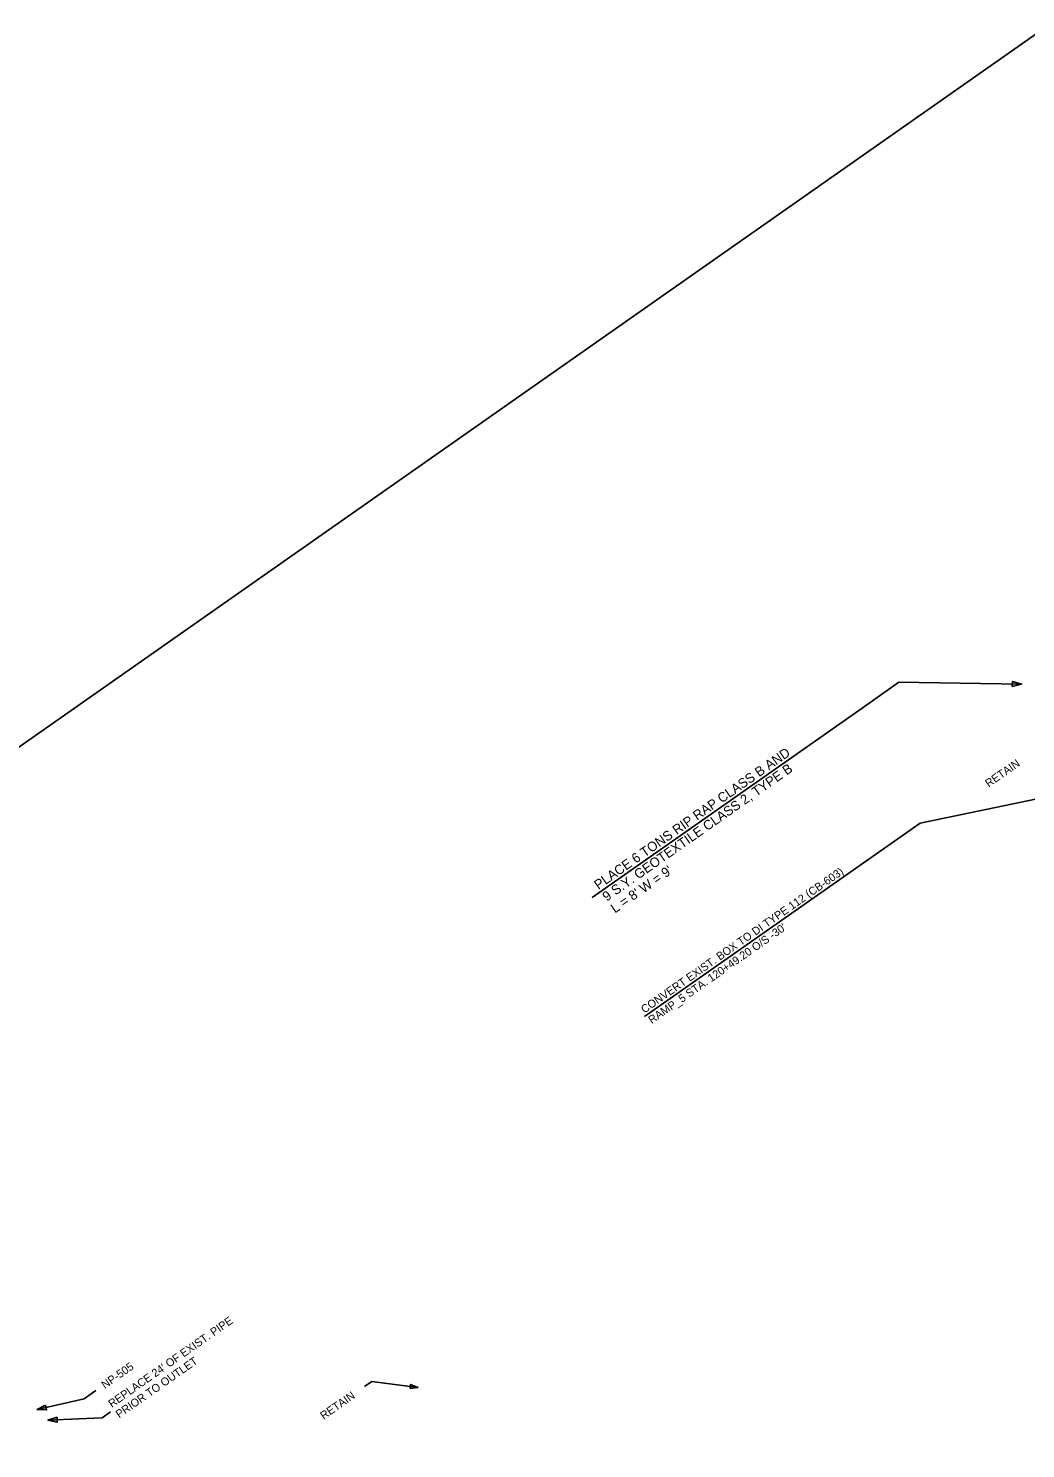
# Model space of a CAD drawing. Extents: x 1605516 to 1608098, y 1090174 to 1092111.
# Drawn here: x 1606742 to 1607365, y 1091123 to 1092010 of the extents above; entities that cross this region are included whole.
import ezdxf

# ---------------------------------------------------------------- set-up
doc = ezdxf.new("R2010")
doc.units = 0
doc.layers.add('RD_HC_CL-reloc', color=7, linetype='Continuous')
doc.layers.add('RD_PD_ALT1_TrvlWay', color=7, linetype='Continuous')

msp = doc.modelspace()

# ---------------------------------------------------------------- linework, layer by layer
at = {"layer": 'RD_HC_CL-reloc'}
msp.add_lwpolyline([(1606406.67, 1091049.1), (1606535.89, 1090871.82), (1606533.04, 1090870.54), (1606692.25, 1090643.55), (1606817.56, 1090464.9), (1608054.17, 1091332.29), (1607913.93, 1091513.97), (1607741.11, 1091760.35), (1607743.52, 1091761.59), (1607623.71, 1091925.97), (1607395.62, 1091983.59), (1607376.3, 1092010.18), (1606278.89, 1091240.8)], close=True, dxfattribs=at)
msp.add_lwpolyline([(1606406.67, 1091049.1), (1606535.89, 1090871.82), (1606533.04, 1090870.54), (1606692.25, 1090643.55), (1606817.56, 1090464.9), (1608054.17, 1091332.29), (1607913.93, 1091513.97), (1607741.11, 1091760.35), (1607743.52, 1091761.59), (1607623.71, 1091925.97), (1607395.62, 1091983.59), (1607376.3, 1092010.18), (1606278.89, 1091240.8)], close=True, dxfattribs=at)
msp.add_lwpolyline([(1606406.67, 1091049.1), (1606535.89, 1090871.82), (1606533.04, 1090870.54), (1606692.25, 1090643.55), (1606817.56, 1090464.9), (1608054.17, 1091332.29), (1607913.93, 1091513.97), (1607741.11, 1091760.35), (1607743.52, 1091761.59), (1607623.71, 1091925.97), (1607395.62, 1091983.59), (1607376.3, 1092010.18), (1606278.89, 1091240.8)], close=True, dxfattribs=at)
msp.add_lwpolyline([(1606406.67, 1091049.1), (1606535.89, 1090871.82), (1606533.04, 1090870.54), (1606692.25, 1090643.55), (1606817.56, 1090464.9), (1608054.17, 1091332.29), (1607913.93, 1091513.97), (1607741.11, 1091760.35), (1607743.52, 1091761.59), (1607623.71, 1091925.97), (1607395.62, 1091983.59), (1607376.3, 1092010.18), (1606278.89, 1091240.8)], close=True, dxfattribs=at)
msp.add_lwpolyline([(1606406.67, 1091049.1), (1606535.89, 1090871.82), (1606533.04, 1090870.54), (1606692.25, 1090643.55), (1606817.56, 1090464.9), (1608054.17, 1091332.29), (1607913.93, 1091513.97), (1607741.11, 1091760.35), (1607743.52, 1091761.59), (1607623.71, 1091925.97), (1607395.62, 1091983.59), (1607376.3, 1092010.18), (1606278.89, 1091240.8)], close=True, dxfattribs=at)
msp.add_lwpolyline([(1606406.67, 1091049.1), (1606535.89, 1090871.82), (1606533.04, 1090870.54), (1606692.25, 1090643.55), (1606817.56, 1090464.9), (1608054.17, 1091332.29), (1607913.93, 1091513.97), (1607741.11, 1091760.35), (1607743.52, 1091761.59), (1607623.71, 1091925.97), (1607395.62, 1091983.59), (1607376.3, 1092010.18), (1606278.89, 1091240.8)], close=True, dxfattribs=at)
at = {"layer": 'RD_PD_ALT1_TrvlWay'}
for p, q in [((1607262.7, 1091585.46), (1607093.91, 1091467.06)), ((1607296.88, 1091511.99), (1607126.71, 1091392.62))]:
    msp.add_line(p, q, dxfattribs=at)
for points in [[(1607262.7, 1091585.46), (1607285.69, 1091601.58), (1607362.42, 1091600.36)], [(1607296.88, 1091511.99), (1607298.9, 1091513.4), (1607413.08, 1091537.21)], [(1606951.77, 1091161.49), (1606956.29, 1091164.65), (1606985.14, 1091160.85)], [(1606783.91, 1091158.93), (1606776.56, 1091153.78), (1606747.05, 1091147.02)], [(1606793.04, 1091145.62), (1606787.78, 1091141.92), (1606753.86, 1091140.37)]]:
    msp.add_lwpolyline(points, dxfattribs=at)
for points in [[(1607356.6, 1091598.9), (1607362.42, 1091600.36), (1607356.65, 1091602)], [(1606980.19, 1091160.2), (1606985.14, 1091160.85), (1606980.52, 1091162.77)], [(1606752.36, 1091149.83), (1606747.05, 1091147.02), (1606753.05, 1091146.8)], [(1606759.58, 1091142.19), (1606753.86, 1091140.37), (1606759.72, 1091139.09)]]:
    msp.add_lwpolyline(points, close=True, dxfattribs=at)

# ---------------------------------------------------------------- texts
for s, height, p in [('PLACE 6 TONS RIP RAP CLASS B AND', 6, (1607097.92, 1091471.71)), ('RETAIN', 5, (1607341.81, 1091535.66)), ('9 S.Y. GEOTEXTILE CLASS 2, TYPE B', 6, (1607103.09, 1091464.34)), ("L = 8' W = 9'", 6, (1607108.26, 1091456.97)), ('CONVERT EXIST. BOX TO DI TYPE 112 (CB-603)', 5, (1607126.66, 1091394.42)), ("RAMP_5 STA. 120+49.20 O/S -30'", 5, (1607131.26, 1091387.87)), ("REPLACE 24' OF EXIST. PIPE", 5, (1606793.82, 1091147.99)), ('PRIOR TO OUTLET', 5, (1606798.41, 1091141.44)), ('NP-505', 5, (1606789.44, 1091159.76)), ('RETAIN', 5, (1606926.23, 1091140.52))]:
    msp.add_text(s, height=height, rotation=35.04683, dxfattribs=at).set_placement(p)

doc.saveas('drawing.dxf')
